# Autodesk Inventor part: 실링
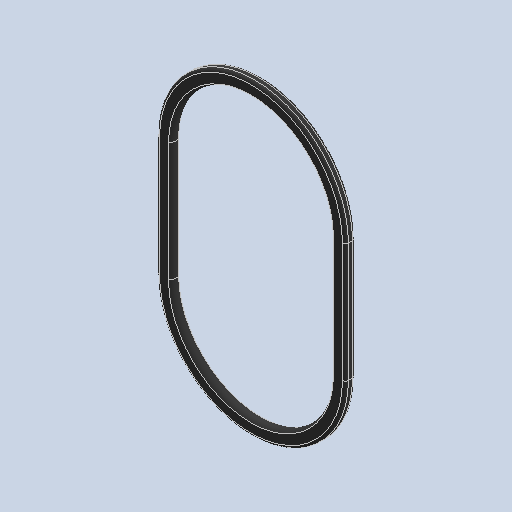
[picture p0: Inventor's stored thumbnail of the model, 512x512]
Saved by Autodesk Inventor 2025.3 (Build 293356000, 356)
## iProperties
Created: 2025-10
Part Number: 실링
Material: 고무
Document SubType Name: Modeling
Designer: PC-04
Density: 0.93 g/cm^3
Appearance: 기본값
Author: jhkim
Sending System: Autodesk Inventor 2026
Preprocessor: ST-DEVELOPER v20.1
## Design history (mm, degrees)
feature "솔리드3"
node "솔리드1"
